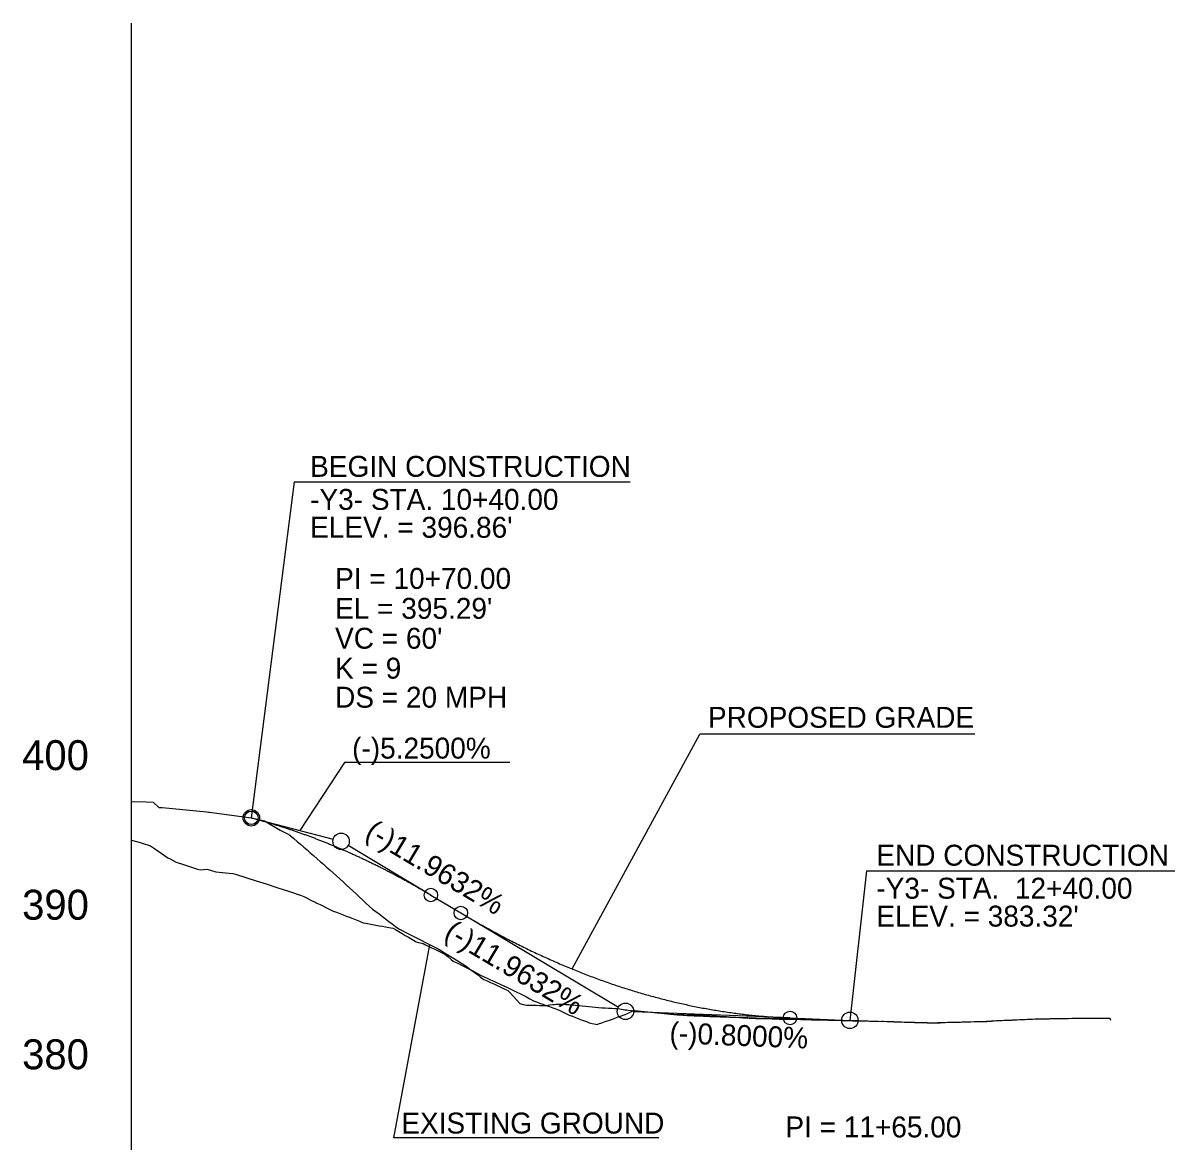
# Model space of a CAD drawing. Extents: x 1625686 to 1640492, y 1161393 to 1175642.
# Drawn here: x 1630170 to 1630554.9, y 1164866.6 to 1165240.7 of the extents above; entities that cross this region are included whole.
import ezdxf

# ---------------------------------------------------------------- set-up
doc = ezdxf.new("R2010")
doc.units = 0
for name, color, linetype in [('Exist Profile Cell', 7, 'Continuous'), ('Exist Vertical Profile Ground Line', 7, 'Continuous'), ('Exist Vertical Profile Vertical Axis Label', 7, 'Continuous'), ('Prop Vertical Profile Curve Label', 7, 'Continuous'), ('Prop Vertical Profile Grade', 7, 'Continuous'), ('Prop Vertical Profile Grade Label', 7, 'Continuous'), ('Prop VPI Label', 7, 'Continuous'), ('Scratch_Level_1', 7, 'Continuous')]:
    doc.layers.add(name, color=color, linetype=linetype)

msp = doc.modelspace()

# ---------------------------------------------------------------- linework, layer by layer
at = {"layer": 'Exist Profile Cell'}
msp.add_line((1630206.28, 1164740.67), (1630206.28, 1165240.67), dxfattribs=at)
at = {"layer": 'Exist Vertical Profile Ground Line'}
msp.add_lwpolyline([(1630206.28, 1164980.42), (1630211.2, 1164980.3), (1630213.51, 1164980.2), (1630215.42, 1164978.4), (1630216.53, 1164978.45), (1630231.42, 1164976.93), (1630231.99, 1164976.86), (1630232.35, 1164976.82), (1630246.24, 1164974.96), (1630250.65, 1164973.97), (1630255.96, 1164970.82), (1630257.23, 1164970.19), (1630258.32, 1164969.65), (1630259.2, 1164969.22), (1630260.51, 1164968.07), (1630261.61, 1164967.11), (1630262.7, 1164966.15), (1630263.8, 1164965.19), (1630264.89, 1164964.23), (1630265.99, 1164963.28), (1630267.08, 1164962.32), (1630268.25, 1164961.31), (1630269.27, 1164960.41), (1630270.36, 1164959.45), (1630271.46, 1164958.49), (1630272.55, 1164957.53), (1630273.65, 1164956.58), (1630274.74, 1164955.61), (1630275.84, 1164954.58), (1630276.93, 1164953.56), (1630278.03, 1164952.55), (1630279.12, 1164951.53), (1630280.22, 1164950.52), (1630281.31, 1164949.51), (1630282.41, 1164948.5), (1630283.5, 1164947.49), (1630284.6, 1164946.49), (1630285.69, 1164945.49), (1630286.79, 1164944.48), (1630287.88, 1164943.65), (1630288.98, 1164942.82), (1630290.07, 1164941.99), (1630291.16, 1164941.16), (1630292.26, 1164940.33), (1630293.35, 1164939.51), (1630294.45, 1164938.69), (1630295.54, 1164937.88), (1630296.64, 1164937.31), (1630297.73, 1164936.74), (1630298.83, 1164936.18), (1630299.92, 1164935.62), (1630301.02, 1164935.05), (1630302.11, 1164934.49), (1630303.21, 1164933.93), (1630304.3, 1164933.37), (1630305.4, 1164932.82), (1630306.49, 1164932.26), (1630307.59, 1164931.7), (1630308.68, 1164931.14), (1630309.78, 1164930.48), (1630310.87, 1164929.82), (1630311.96, 1164929.15), (1630313.06, 1164928.49), (1630314.15, 1164927.82), (1630315.25, 1164927.15), (1630316.34, 1164926.48), (1630317.44, 1164925.8), (1630318.53, 1164924.99), (1630319.63, 1164924.17), (1630320.72, 1164923.36), (1630321.82, 1164922.54), (1630322.91, 1164921.73), (1630324, 1164920.93), (1630325.1, 1164920.44), (1630326.19, 1164919.94), (1630327.29, 1164919.44), (1630328.38, 1164918.94), (1630329.48, 1164918.43), (1630330.57, 1164917.92), (1630331.95, 1164917.28), (1630332.76, 1164916.41), (1630333.85, 1164915.22), (1630334.95, 1164914.04), (1630336.04, 1164912.89), (1630337.14, 1164912.59), (1630338.23, 1164912.34), (1630339.33, 1164912.33), (1630340.42, 1164912.31), (1630341.52, 1164912.3), (1630342.61, 1164912.28), (1630343.71, 1164912.26), (1630344.8, 1164912.26), (1630345.89, 1164912.41), (1630346.99, 1164912.55), (1630347.42, 1164912.61), (1630348.08, 1164912.62), (1630349.18, 1164912.64), (1630350.27, 1164912.66), (1630350.81, 1164912.67), (1630351.37, 1164912.61), (1630352.46, 1164912.51), (1630353.56, 1164912.4), (1630354.65, 1164912.3), (1630355.75, 1164912.19), (1630356.84, 1164912.08), (1630357.93, 1164911.97), (1630359.03, 1164911.86), (1630360.12, 1164911.75), (1630361.22, 1164911.64), (1630362.31, 1164911.53), (1630363.41, 1164911.48), (1630364.5, 1164911.42), (1630365.6, 1164911.37), (1630366.69, 1164911.31), (1630367.78, 1164911.25), (1630368.88, 1164911.18), (1630369.97, 1164911), (1630371.07, 1164910.83), (1630371.73, 1164910.73), (1630372.16, 1164910.69), (1630373.26, 1164910.59), (1630374.35, 1164910.49), (1630375.46, 1164910.39), (1630376.54, 1164910.29), (1630377.64, 1164910.19), (1630378.73, 1164910.09), (1630379.82, 1164909.99), (1630380.25, 1164909.95), (1630380.92, 1164909.9), (1630382.01, 1164909.8), (1630383.11, 1164909.71), (1630384.2, 1164909.61), (1630385.3, 1164909.52), (1630386.39, 1164909.42), (1630387.49, 1164909.32), (1630388.08, 1164909.27), (1630388.65, 1164909.32), (1630389.67, 1164909.4), (1630390.93, 1164909.48), (1630391.86, 1164909.38), (1630392.96, 1164909.27), (1630394.05, 1164909.17), (1630395.15, 1164909.11), (1630396.24, 1164909.05), (1630397.34, 1164908.99), (1630397.98, 1164908.95), (1630398.43, 1164908.92), (1630399.53, 1164908.86), (1630400.62, 1164908.79), (1630401.71, 1164908.72), (1630402.81, 1164908.65), (1630403.9, 1164908.58), (1630405, 1164908.51), (1630406.09, 1164908.44), (1630407.19, 1164908.37), (1630408.28, 1164908.3), (1630409.38, 1164908.22), (1630410.47, 1164908.15), (1630411.57, 1164908.08), (1630412.66, 1164908), (1630413.44, 1164907.95), (1630413.75, 1164907.95), (1630414.85, 1164907.93), (1630415.94, 1164907.92), (1630417.04, 1164907.9), (1630418.19, 1164907.89), (1630419.23, 1164907.85), (1630420.32, 1164907.8), (1630421.42, 1164907.76), (1630422.66, 1164907.71), (1630423.6, 1164907.7), (1630424.7, 1164907.69), (1630425.79, 1164907.68), (1630426.89, 1164907.67), (1630427.98, 1164907.65), (1630429.08, 1164907.64), (1630430.17, 1164907.62), (1630431.27, 1164907.6), (1630432.36, 1164907.58), (1630433.46, 1164907.56), (1630434.55, 1164907.54), (1630435.64, 1164907.52), (1630436.74, 1164907.49), (1630437.83, 1164907.47), (1630438.93, 1164907.44), (1630440.02, 1164907.41), (1630441.12, 1164907.38), (1630442.21, 1164907.35), (1630443.94, 1164907.3), (1630448.81, 1164907.19), (1630459.25, 1164906.87), (1630460.1, 1164906.85), (1630460.96, 1164906.82), (1630461.82, 1164906.79), (1630462.68, 1164906.77), (1630463.54, 1164906.74), (1630464.39, 1164906.71), (1630465.25, 1164906.69), (1630466.11, 1164906.66), (1630466.97, 1164906.63), (1630467.83, 1164906.6), (1630468.91, 1164906.57), (1630469.54, 1164906.56), (1630470.4, 1164906.51), (1630471.26, 1164906.51), (1630471.73, 1164906.51), (1630472.11, 1164906.49), (1630472.97, 1164906.48), (1630473.83, 1164906.46), (1630474.69, 1164906.45), (1630475.55, 1164906.45), (1630475.86, 1164906.45), (1630476.4, 1164906.49), (1630477.26, 1164906.56), (1630478.12, 1164906.6), (1630478.98, 1164906.64), (1630479.87, 1164906.68), (1630480.69, 1164906.68), (1630481.55, 1164906.67), (1630482.42, 1164906.66), (1630483.27, 1164906.7), (1630483.74, 1164906.72), (1630484.12, 1164906.73), (1630485.03, 1164906.74), (1630485.84, 1164906.77), (1630486.7, 1164906.8), (1630487.79, 1164906.83), (1630488.5, 1164906.85), (1630489.27, 1164906.85), (1630490.19, 1164906.86), (1630490.99, 1164906.88), (1630491.97, 1164906.91), (1630492.75, 1164906.98), (1630493.56, 1164907.04), (1630494.11, 1164907.08), (1630494.42, 1164907.11), (1630495.29, 1164907.19), (1630496.28, 1164907.22), (1630496.99, 1164907.25), (1630497.85, 1164907.3), (1630498.71, 1164907.32), (1630499.84, 1164907.36), (1630500.42, 1164907.38), (1630501.28, 1164907.42), (1630502.14, 1164907.46), (1630503, 1164907.5), (1630503.85, 1164907.55), (1630504.71, 1164907.6), (1630505.57, 1164907.64), (1630506.43, 1164907.67), (1630507.29, 1164907.69), (1630508.14, 1164907.72), (1630509, 1164907.74), (1630509.86, 1164907.76), (1630510.72, 1164907.78), (1630511.57, 1164907.8), (1630512.43, 1164907.81), (1630512.86, 1164907.82), (1630513.29, 1164907.83), (1630514.15, 1164907.85), (1630515.01, 1164907.87), (1630515.36, 1164907.88), (1630516, 1164907.89), (1630516.72, 1164907.91), (1630517.86, 1164907.92), (1630518.44, 1164907.93), (1630519.29, 1164907.93), (1630520.37, 1164907.94), (1630521.01, 1164907.94), (1630521.87, 1164907.94), (1630522.89, 1164907.94), (1630523.58, 1164907.95), (1630524.54, 1164907.96), (1630525.42, 1164907.98), (1630526.16, 1164908), (1630526.63, 1164908.01), (1630527.02, 1164908.01), (1630527.95, 1164908.02), (1630528.73, 1164908.02), (1630529.77, 1164908.03), (1630530.5, 1164908.03), (1630531.3, 1164908.03), (1630532.16, 1164908.04), (1630533.07, 1164908.04)], dxfattribs=at)
at = {"layer": 'Prop Vertical Profile Curve Label'}
for centre in [(1630246.28, 1164974.97), (1630306.28, 1164949.15), (1630316.28, 1164943.17), (1630426.28, 1164908.07)]:
    msp.add_circle(centre, 2.25, dxfattribs=at)
at = {"layer": 'Prop Vertical Profile Grade'}
for p, q in [((1630306.28, 1164949.15), (1630316.28, 1164943.17)), ((1630426.28, 1164908.07), (1630446.28, 1164907.27))]:
    msp.add_line(p, q, dxfattribs=at)
for points in [[(1630246.28, 1164974.97), (1630247.48, 1164974.66), (1630248.68, 1164974.33), (1630249.88, 1164973.99), (1630251.08, 1164973.65), (1630252.28, 1164973.3), (1630253.48, 1164972.94), (1630254.68, 1164972.57), (1630255.88, 1164972.2), (1630257.08, 1164971.81), (1630258.28, 1164971.42), (1630259.48, 1164971.02), (1630260.68, 1164970.61), (1630261.88, 1164970.2), (1630263.08, 1164969.77), (1630264.28, 1164969.34), (1630265.48, 1164968.9), (1630266.68, 1164968.46), (1630267.88, 1164968), (1630269.08, 1164967.54), (1630270.28, 1164967.06), (1630271.48, 1164966.58), (1630272.68, 1164966.09), (1630273.88, 1164965.6), (1630275.08, 1164965.09), (1630276.28, 1164964.58), (1630277.48, 1164964.06), (1630278.68, 1164963.53), (1630279.88, 1164963), (1630281.08, 1164962.45), (1630282.28, 1164961.9), (1630283.48, 1164961.34), (1630284.68, 1164960.77), (1630285.88, 1164960.19), (1630287.08, 1164959.61), (1630288.28, 1164959.02), (1630289.48, 1164958.41), (1630290.68, 1164957.81), (1630291.88, 1164957.19), (1630293.08, 1164956.56), (1630294.28, 1164955.93), (1630295.48, 1164955.29), (1630296.68, 1164954.64), (1630297.88, 1164953.98), (1630299.08, 1164953.32), (1630300.28, 1164952.64), (1630301.48, 1164951.96), (1630302.68, 1164951.27), (1630303.88, 1164950.57), (1630305.08, 1164949.87), (1630306.28, 1164949.15)], [(1630316.28, 1164943.17), (1630318.48, 1164941.87), (1630320.68, 1164940.59), (1630322.88, 1164939.34), (1630325.08, 1164938.11), (1630327.28, 1164936.9), (1630329.48, 1164935.72), (1630331.68, 1164934.56), (1630333.88, 1164933.43), (1630336.08, 1164932.32), (1630338.28, 1164931.24), (1630340.48, 1164930.18), (1630342.68, 1164929.15), (1630344.88, 1164928.14), (1630347.08, 1164927.16), (1630349.28, 1164926.2), (1630351.48, 1164925.26), (1630353.68, 1164924.35), (1630355.88, 1164923.46), (1630358.08, 1164922.6), (1630360.28, 1164921.77), (1630362.48, 1164920.95), (1630364.68, 1164920.17), (1630366.88, 1164919.4), (1630369.08, 1164918.66), (1630371.28, 1164917.95), (1630373.48, 1164917.26), (1630375.68, 1164916.59), (1630377.88, 1164915.95), (1630380.08, 1164915.34), (1630382.28, 1164914.75), (1630384.48, 1164914.18), (1630386.68, 1164913.64), (1630388.88, 1164913.12), (1630391.08, 1164912.63), (1630393.28, 1164912.16), (1630395.48, 1164911.71), (1630397.68, 1164911.29), (1630399.88, 1164910.9), (1630402.08, 1164910.53), (1630404.28, 1164910.18), (1630406.48, 1164909.86), (1630408.68, 1164909.56), (1630410.88, 1164909.29), (1630413.08, 1164909.04), (1630415.28, 1164908.82), (1630417.48, 1164908.62), (1630419.68, 1164908.45), (1630421.88, 1164908.3), (1630424.08, 1164908.17), (1630426.28, 1164908.07)]]:
    msp.add_spline(points, degree=3, dxfattribs=at)
at = {"layer": 'Prop Vertical Profile Grade Label'}
for p, q in [((1630260.61, 1165087.24), (1630246.28, 1164974.97)), ((1630260.61, 1165087.24), (1630372.81, 1165087.24)), ((1630353.43, 1164924.45), (1630396.12, 1165002.91)), ((1630488.03, 1165002.91), (1630396.12, 1165002.91)), ((1630277.4, 1164993.52), (1630262.48, 1164970.72)), ((1630332.65, 1164993.52), (1630277.4, 1164993.52)), ((1630451.78, 1164957.25), (1630446.28, 1164907.27)), ((1630451.78, 1164957.25), (1630554.88, 1164957.25))]:
    msp.add_line(p, q, dxfattribs=at)
at = {"layer": 'Prop VPI Label'}
for p, q in [((1630246.28, 1164974.97), (1630273.62, 1164967.8)), ((1630306.28, 1164949.15), (1630278.64, 1164965.69)), ((1630316.28, 1164943.17), (1630368.92, 1164911.69)), ((1630293.87, 1164867.98), (1630305.94, 1164932.54)), ((1630426.28, 1164908.07), (1630374.03, 1164910.16)), ((1630382.47, 1164867.98), (1630293.87, 1164867.98))]:
    msp.add_line(p, q, dxfattribs=at)
for centre in [(1630246.28, 1164974.97), (1630276.28, 1164967.1), (1630371.28, 1164910.27), (1630446.28, 1164907.27)]:
    msp.add_circle(centre, 2.75, dxfattribs=at)
at = {"layer": 'Scratch_Level_1'}
for points in [[(1630206.28, 1164967.45), (1630209.13, 1164966.67), (1630209.79, 1164966.46), (1630212.65, 1164965.58), (1630213.91, 1164964.74), (1630218.37, 1164961.59), (1630219.13, 1164961.21), (1630221.23, 1164960.19), (1630223.64, 1164959.35), (1630228.31, 1164957.76), (1630229.34, 1164957.53), (1630231.52, 1164957.76), (1630234.39, 1164956.9), (1630238.84, 1164956.47), (1630240.15, 1164956.33), (1630240.6, 1164956.23), (1630241.32, 1164956.02), (1630247.86, 1164953.96), (1630249.04, 1164953.61), (1630251.24, 1164952.86), (1630254.48, 1164951.82), (1630257.23, 1164950.93), (1630258.32, 1164950.58), (1630259.42, 1164950.22), (1630260.68, 1164949.81), (1630261.61, 1164949.49), (1630262.7, 1164949.11), (1630263.27, 1164948.92), (1630263.8, 1164948.66), (1630264.89, 1164948.12), (1630265.99, 1164947.58), (1630267.08, 1164947.03), (1630267.46, 1164946.84), (1630268.17, 1164946.49), (1630269.27, 1164945.95), (1630270.36, 1164945.41), (1630271.46, 1164944.87), (1630272.55, 1164944.32), (1630273.65, 1164943.79), (1630274.74, 1164943.38), (1630275.84, 1164942.97), (1630276.93, 1164942.55), (1630278.03, 1164942.13), (1630279.12, 1164941.72), (1630279.86, 1164941.43), (1630280.22, 1164941.29), (1630281.31, 1164940.84), (1630282.41, 1164940.4), (1630283.61, 1164939.9), (1630284.6, 1164939.72), (1630285.69, 1164939.52), (1630286.79, 1164939.32), (1630287.88, 1164939.12), (1630288.98, 1164938.91), (1630290.07, 1164938.71), (1630291.16, 1164938.5), (1630292.26, 1164938.31), (1630293.65, 1164938.07), (1630294.45, 1164937.6), (1630295.54, 1164936.95), (1630296.64, 1164936.31), (1630297.73, 1164935.67), (1630298.83, 1164935.02), (1630299.92, 1164934.38), (1630301.02, 1164933.73), (1630301.33, 1164933.54), (1630302.11, 1164933.34), (1630303.21, 1164933.05), (1630303.65, 1164932.93), (1630304.3, 1164932.61), (1630305.4, 1164932.08), (1630306.49, 1164931.55), (1630307.59, 1164931.02), (1630308.68, 1164930.5), (1630309.78, 1164929.97), (1630310.98, 1164929.39), (1630311.96, 1164928.56), (1630313.06, 1164927.63), (1630313.7, 1164927.08), (1630314.15, 1164926.88), (1630315.25, 1164926.41), (1630315.56, 1164926.27), (1630316.34, 1164925.86), (1630317.44, 1164925.28), (1630318.53, 1164924.7), (1630319.63, 1164924.12), (1630320.72, 1164923.54), (1630321.82, 1164922.97), (1630322.91, 1164922.39), (1630323.53, 1164922.07), (1630324.08, 1164921.81), (1630325.1, 1164921.33), (1630326.19, 1164920.82), (1630327.29, 1164920.31), (1630328.38, 1164919.81), (1630329.48, 1164919.32), (1630330.83, 1164918.71), (1630331.67, 1164918.31), (1630332.76, 1164917.79), (1630333.85, 1164917.26), (1630334.95, 1164916.74)], [(1630334.95, 1164916.74), (1630336.04, 1164916.22), (1630337.14, 1164915.69), (1630338.23, 1164915.15), (1630339.33, 1164914.49), (1630340.53, 1164913.77), (1630341.52, 1164913.42), (1630342.61, 1164913.03), (1630343.71, 1164912.65), (1630344.8, 1164912.26), (1630345.89, 1164911.87), (1630346.99, 1164911.48), (1630348.08, 1164911.1), (1630348.63, 1164910.93), (1630349.18, 1164910.65), (1630350.27, 1164910.11), (1630351.37, 1164909.58), (1630352.46, 1164909.05), (1630353.56, 1164908.63), (1630354.65, 1164908.21), (1630355.75, 1164907.8), (1630356.84, 1164907.38), (1630357.93, 1164906.97), (1630358.27, 1164906.85), (1630359.17, 1164906.47), (1630359.69, 1164906.32), (1630360.12, 1164906.24), (1630361.36, 1164906), (1630361.84, 1164905.91), (1630362.31, 1164906.08), (1630363.41, 1164906.47), (1630364.5, 1164906.84), (1630365.6, 1164907.2), (1630366.24, 1164907.41), (1630366.69, 1164907.58), (1630367.78, 1164907.99), (1630368.88, 1164908.39), (1630369.97, 1164908.77), (1630370.5, 1164908.95), (1630371.23, 1164909.21), (1630372.16, 1164909.69), (1630373.26, 1164910.24), (1630374.03, 1164910.62), (1630374.35, 1164910.59), (1630375.45, 1164910.48), (1630376.54, 1164910.37), (1630377.64, 1164910.26), (1630378.73, 1164910.14), (1630379.82, 1164910.03), (1630380.92, 1164909.92), (1630382.13, 1164909.79), (1630383.11, 1164909.7), (1630384.2, 1164909.6), (1630385.3, 1164909.49), (1630386.39, 1164909.38), (1630387.49, 1164909.27), (1630387.98, 1164909.22), (1630388.58, 1164909.16), (1630389.3, 1164909.08), (1630389.67, 1164909.06), (1630390.41, 1164909.02), (1630390.77, 1164909), (1630391.86, 1164908.93), (1630392.54, 1164908.89), (1630392.96, 1164908.86), (1630394.22, 1164908.77), (1630395.15, 1164908.76), (1630396.48, 1164908.72), (1630397.34, 1164908.69), (1630398.01, 1164908.66), (1630398.43, 1164908.64), (1630399.06, 1164908.61), (1630399.53, 1164908.59), (1630400.87, 1164908.53), (1630401.71, 1164908.53), (1630402.89, 1164908.47), (1630403.9, 1164908.45), (1630404.27, 1164908.44), (1630405, 1164908.4), (1630406.09, 1164908.38), (1630407.19, 1164908.35), (1630408.28, 1164908.31), (1630409.53, 1164908.26), (1630410.47, 1164908.24), (1630410.94, 1164908.22), (1630411.57, 1164908.2), (1630412.19, 1164908.17), (1630412.66, 1164908.16), (1630413.75, 1164908.13), (1630414.32, 1164908.11), (1630414.86, 1164908.1), (1630415.94, 1164908.05), (1630416.64, 1164908.01), (1630417.04, 1164908.01), (1630417.55, 1164908), (1630418.13, 1164907.97), (1630418.55, 1164907.95), (1630419.23, 1164907.94), (1630420.46, 1164907.89), (1630420.92, 1164907.9), (1630421.42, 1164907.88)], [(1630421.42, 1164907.88), (1630422.51, 1164907.85), (1630422.99, 1164907.83), (1630423.6, 1164907.79), (1630424.25, 1164907.74), (1630424.7, 1164907.77), (1630425.79, 1164907.83), (1630426.13, 1164907.82), (1630426.92, 1164907.79), (1630428, 1164907.67), (1630428.53, 1164907.67), (1630429.08, 1164907.62), (1630429.86, 1164907.55), (1630430.17, 1164907.56), (1630431.33, 1164907.58), (1630431.72, 1164907.56), (1630432.45, 1164907.56), (1630433.46, 1164907.48), (1630434.16, 1164907.42), (1630434.55, 1164907.43), (1630435.64, 1164907.45), (1630436.23, 1164907.46), (1630437.02, 1164907.43), (1630437.83, 1164907.41), (1630438.93, 1164907.37), (1630440.02, 1164907.33), (1630441.12, 1164907.33), (1630442.84, 1164907.31), (1630444.53, 1164907.11), (1630445.78, 1164907.16), (1630447.27, 1164907.12), (1630448.16, 1164907.02), (1630448.71, 1164907.05), (1630449.98, 1164906.95), (1630452.04, 1164907.06), (1630453.62, 1164906.91), (1630454.59, 1164906.95), (1630455.43, 1164906.91), (1630456.81, 1164906.96), (1630457.52, 1164906.94), (1630458.67, 1164906.93), (1630459.25, 1164906.9), (1630460.1, 1164906.87), (1630460.45, 1164906.85), (1630460.96, 1164906.84), (1630461.82, 1164906.81), (1630462.72, 1164906.72), (1630463.54, 1164906.72), (1630464.56, 1164906.65), (1630465.25, 1164906.68), (1630466.18, 1164906.72), (1630466.97, 1164906.69), (1630467.83, 1164906.62), (1630468.27, 1164906.59), (1630468.97, 1164906.57), (1630469.54, 1164906.54), (1630470.4, 1164906.51), (1630471.26, 1164906.51), (1630471.73, 1164906.51), (1630472.11, 1164906.5), (1630472.97, 1164906.49), (1630473.83, 1164906.46), (1630474.69, 1164906.46), (1630475.65, 1164906.52), (1630476.4, 1164906.53), (1630477.26, 1164906.55), (1630477.8, 1164906.57), (1630478.12, 1164906.59), (1630478.98, 1164906.64), (1630479.87, 1164906.68), (1630480.69, 1164906.68), (1630481.55, 1164906.67), (1630482.42, 1164906.66), (1630483.27, 1164906.7), (1630483.74, 1164906.72), (1630484.12, 1164906.73), (1630485.03, 1164906.74), (1630485.84, 1164906.77), (1630486.7, 1164906.8), (1630487.79, 1164906.83), (1630488.49, 1164906.85), (1630489.27, 1164906.85), (1630490.19, 1164906.86), (1630490.99, 1164906.91), (1630491.84, 1164906.95), (1630492.75, 1164906.98), (1630493.56, 1164907.05), (1630493.89, 1164907.08), (1630494.42, 1164907.12), (1630495.29, 1164907.19), (1630496.28, 1164907.22), (1630496.99, 1164907.25), (1630497.85, 1164907.3), (1630498.71, 1164907.32), (1630499.56, 1164907.35), (1630500.42, 1164907.38), (1630500.73, 1164907.39), (1630501.28, 1164907.42), (1630502.14, 1164907.46), (1630503.02, 1164907.51), (1630503.85, 1164907.55)], [(1630503.85, 1164907.55), (1630504.71, 1164907.6), (1630505.57, 1164907.64), (1630506.43, 1164907.67), (1630507.29, 1164907.69), (1630508.14, 1164907.72), (1630509, 1164907.74), (1630509.86, 1164907.76), (1630510.72, 1164907.78), (1630511.57, 1164907.8), (1630512.43, 1164907.81), (1630512.98, 1164907.82), (1630513.29, 1164907.83), (1630514.15, 1164907.85), (1630515.01, 1164907.87), (1630515.39, 1164907.88), (1630516, 1164907.9), (1630516.72, 1164907.91), (1630518, 1164907.92), (1630518.44, 1164907.93), (1630519.29, 1164907.93), (1630520.37, 1164907.94), (1630521.01, 1164907.94), (1630521.87, 1164907.94), (1630522.89, 1164907.94), (1630523.64, 1164907.95), (1630524.44, 1164907.96), (1630525.42, 1164907.98), (1630526.16, 1164908), (1630526.63, 1164908.01), (1630527.02, 1164908.01), (1630527.95, 1164908.02), (1630528.73, 1164908.02), (1630529.77, 1164908.03), (1630530.5, 1164908.03), (1630531.3, 1164908.03), (1630532.16, 1164908.04), (1630533.07, 1164908.04), (1630533.35, 1164907.3)]]:
    msp.add_lwpolyline(points, dxfattribs=at)

# ---------------------------------------------------------------- texts
at = {"layer": 'Exist Vertical Profile Vertical Axis Label'}
for s, p in [('400', (1630169.71, 1164990.92)), ('390', (1630169.71, 1164940.92)), ('380', (1630169.71, 1164890.92))]:
    msp.add_text(s, height=10, dxfattribs=at).set_placement(p)
at = {"layer": 'Prop Vertical Profile Curve Label'}
for s, p in [("VC = 60'", (1630274.27, 1165031.5)), ('K = 9', (1630274.27, 1165021.5)), ('DS = 20 MPH', (1630274.27, 1165011.79))]:
    msp.add_text(s, height=7, dxfattribs=at).set_placement(p)
at = {"layer": 'Prop Vertical Profile Grade Label'}
for s, p in [('PROPOSED GRADE', (1630398.85, 1165005.07)), ('(-)5.2500%', (1630279.97, 1164994.77))]:
    msp.add_text(s, height=7, dxfattribs=at).set_placement(p)
for s, rotation, p in [('(-)11.9632%', 329.1139, (1630283.88, 1164968.64)), ('(-)11.9632%', 329.1139, (1630310.3, 1164935.1)), ('(-)0.8000%', 357.7094, (1630385.9, 1164899.68))]:
    msp.add_text(s, height=7, rotation=rotation, dxfattribs=at).set_placement(p)
at = {"layer": 'Prop VPI Label'}
for s, p in [('BEGIN CONSTRUCTION', (1630265.94, 1165088.96)), ('-Y3- STA. 10+40.00', (1630265.94, 1165077.92)), ("ELEV. = 396.86'", (1630265.94, 1165068.6)), ('PI = 10+70.00', (1630274.27, 1165051.5)), ("EL = 395.29'", (1630274.27, 1165041.5)), ('END CONSTRUCTION', (1630455.11, 1164958.97)), ('-Y3- STA.  12+40.00', (1630455.11, 1164947.93)), ("ELEV. = 383.32'", (1630455.11, 1164938.61)), ('EXISTING GROUND', (1630296.39, 1164869.42)), ('PI = 11+65.00', (1630424.72, 1164868.13))]:
    msp.add_text(s, height=7, dxfattribs=at).set_placement(p)

doc.saveas('drawing.dxf')
